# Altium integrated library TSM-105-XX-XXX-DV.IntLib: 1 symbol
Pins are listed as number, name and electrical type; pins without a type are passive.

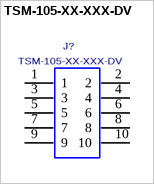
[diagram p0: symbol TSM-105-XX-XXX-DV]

## TSM-105-XX-XXX-DV
designator J?
DOUBLE ROW SURFACE MOUNT TERMINAL STRIP; MANUFACTURER: SAMTEC
footprint TSM-105-XX-XXX-DV
pins: 1, 2, 3, 4, 5, 6, 7, 8, 9, 10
